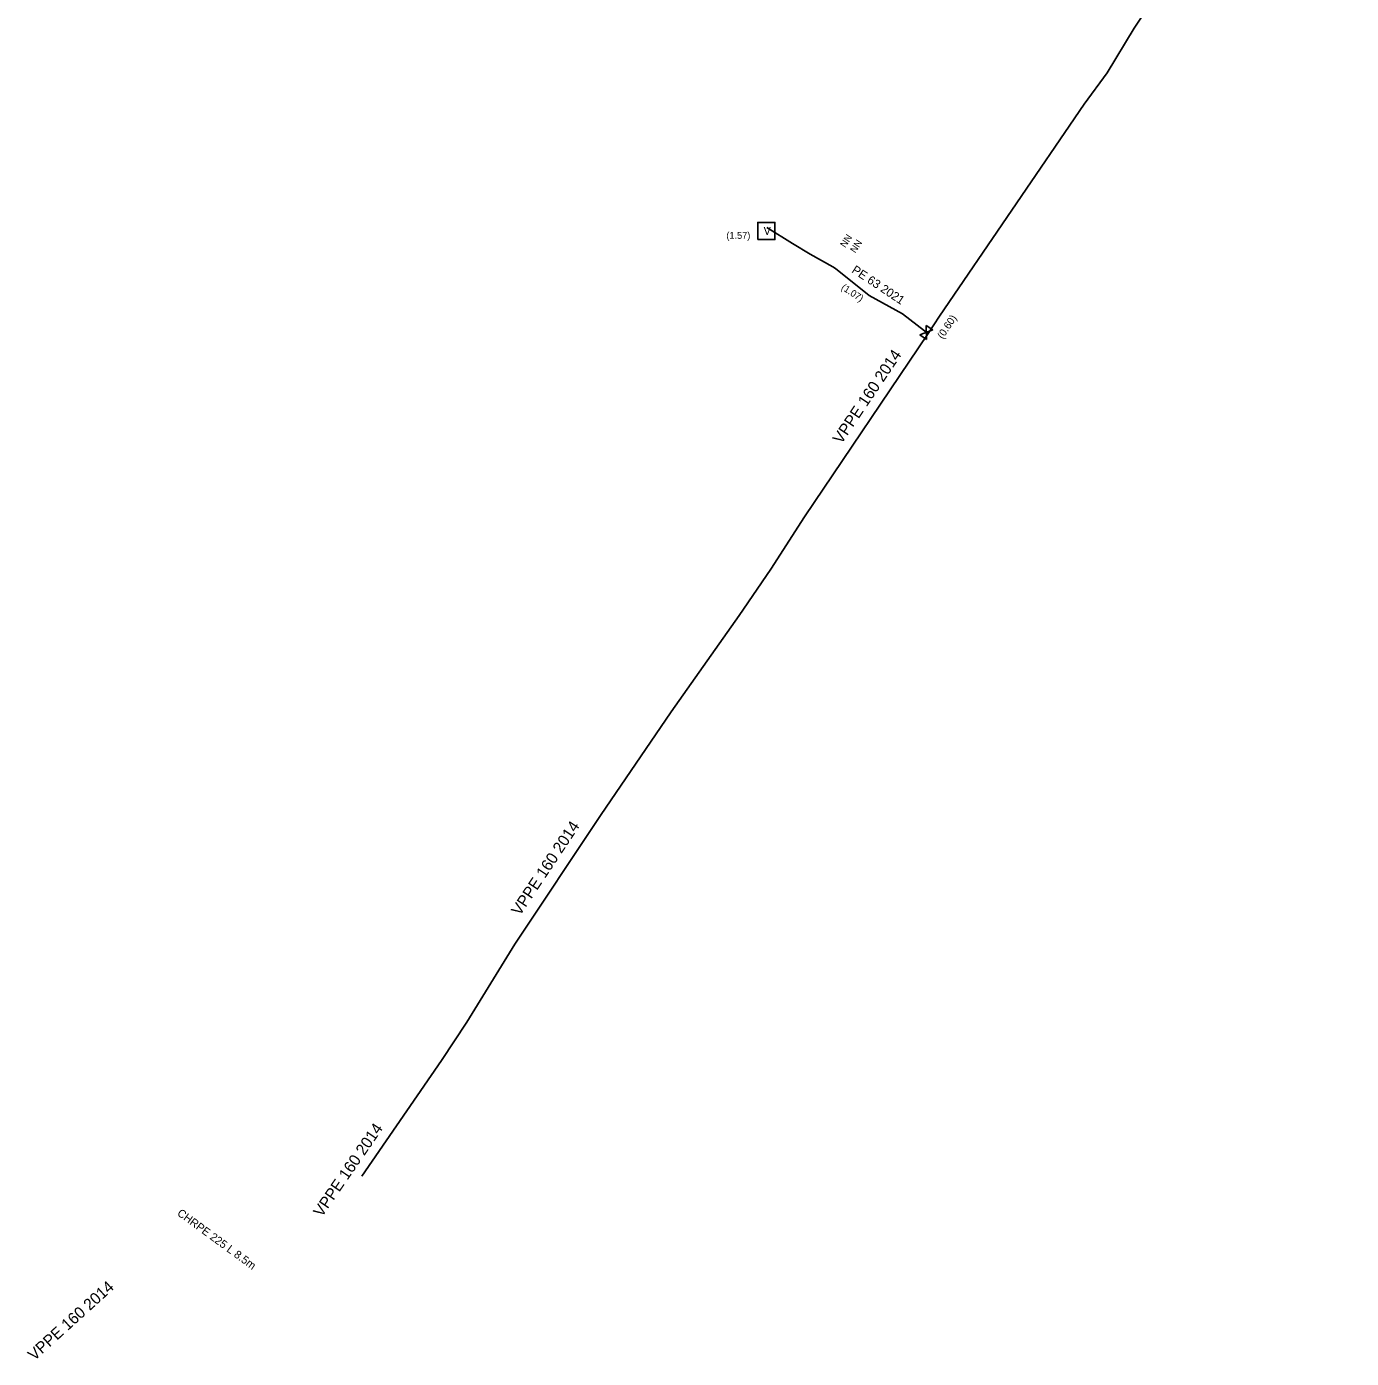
# Model space of a CAD drawing. Extents: x -539692 to -539259, y -1156467 to -1155971.
# Drawn here: x -539411.7 to -539295.8, y -1156214.5 to -1156098 of the extents above; entities that cross this region are included whole.
import ezdxf

# ---------------------------------------------------------------- set-up
doc = ezdxf.new("R2010")
doc.units = 0
for name, color, linetype in [('Vrstva 11', 7, 'Continuous'), ('Vrstva 32', 7, 'Continuous'), ('Vrstva 37', 7, 'Continuous'), ('Vrstva 55', 7, 'Continuous'), ('Vrstva 56', 7, 'Continuous'), ('Vrstva 57', 7, 'Continuous'), ('Vrstva 58', 7, 'Continuous'), ('Vrstva 7', 7, 'Continuous')]:
    doc.layers.add(name, color=color, linetype=linetype)

msp = doc.modelspace()

# ---------------------------------------------------------------- linework, layer by layer
at = {"layer": 'Vrstva 11'}
for p, q in [((-539344.656, -1156116.967), (-539346.92, -1156115.57)), ((-539332.81, -1156124.85), (-539332.95, -1156124.76))]:
    msp.add_line(p, q, dxfattribs=at)
msp.add_lwpolyline([(-539332.95, -1156124.76), (-539333.12, -1156124.63), (-539335.04, -1156123.12), (-539337.95, -1156121.52), (-539340.89, -1156119.17), (-539341.15, -1156119.02), (-539343.11, -1156117.92), (-539344.656, -1156116.967)], dxfattribs=at)
at = {"layer": 'Vrstva 32'}
for p, q in [((-539332.972, -1156124.144), (-539332.93, -1156125.377)), ((-539332.972, -1156124.144), (-539332.377, -1156124.535)), ((-539332.377, -1156124.535), (-539333.523, -1156124.985)), ((-539333.523, -1156124.985), (-539332.93, -1156125.377))]:
    msp.add_line(p, q, dxfattribs=at)
at = {"layer": 'Vrstva 37'}
msp.add_lwpolyline([(-539347.71, -1156116.629), (-539346.21, -1156116.631), (-539346.21, -1156115.131), (-539347.711, -1156115.13)], close=True, dxfattribs=at)
at = {"layer": 'Vrstva 7'}
for points in [[(-539332.81, -1156124.85), (-539331.81, -1156123.34), (-539319.14, -1156104.79), (-539317.13, -1156102.06), (-539314.79, -1156098.13), (-539307.94, -1156087.91), (-539298.59, -1156074), (-539295.78, -1156069.878)], [(-539382.349, -1156198.586), (-539375.38, -1156188.45), (-539373.14, -1156185.1), (-539368.96, -1156178.29), (-539361.47, -1156167.04), (-539355.27, -1156157.95), (-539349.34, -1156149.54), (-539346.55, -1156145.47), (-539343.61, -1156140.88), (-539332.81, -1156124.85)]]:
    msp.add_lwpolyline(points, dxfattribs=at)

# ---------------------------------------------------------------- texts
at = {"layer": 'Vrstva 37'}
msp.add_text('V', height=0.7, dxfattribs=at).set_placement((-539347.188, -1156116.23))
at = {"layer": 'Vrstva 55'}
for rotation, p in [(56.06937, (-539340.39, -1156134.59)), (56.34522, (-539368.51, -1156175.86)), (55.48887, (-539385.836, -1156202.231)), (42.11451, (-539410.99, -1156214.78))]:
    msp.add_text('VPPE 160 2014', height=1, rotation=rotation, dxfattribs=at).set_placement(p)
at = {"layer": 'Vrstva 56'}
msp.add_text('PE 63 2021', height=0.75, rotation=326.5542, dxfattribs=at).set_placement((-539339.55, -1156119.47))
at = {"layer": 'Vrstva 57'}
msp.add_text('CHRPE 225 L 8.5m', height=0.7, rotation=323.80677, dxfattribs=at).set_placement((-539398.549, -1156201.952))
at = {"layer": 'Vrstva 58'}
msp.add_text('(1.57)', height=0.6, dxfattribs=at).set_placement((-539350.45, -1156116.57))
for s, height, rotation, p in [('NN', 0.6, 56.48544, (-539340.052, -1156117.4)), ('NN', 0.6, 56.48544, (-539339.176, -1156117.866)), ('(1.07)', 0.6, 326.72907, (-539340.46, -1156120.96)), ('(0.60)', 0.65, 56.48544, (-539331.516, -1156125.384))]:
    msp.add_text(s, height=height, rotation=rotation, dxfattribs=at).set_placement(p)

doc.saveas('drawing.dxf')
